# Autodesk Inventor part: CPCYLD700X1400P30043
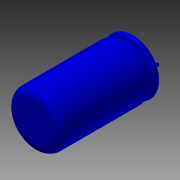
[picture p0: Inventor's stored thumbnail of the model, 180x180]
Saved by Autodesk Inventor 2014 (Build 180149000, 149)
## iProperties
Shininess: 64.0
Length Units: 11272
Angle Units: 11279
Time Units: 11290
Mass Units: 11286
Length Display Precision: 3
Angle Display Precision: 2
Compacted: True
Part Number: CPCYLD700X1400P30043
Document SubType Name: Modeling
Created: 2003-04
Designer: t_enrig
Manufacturer: Standard
Standards Organization: Custom
Density: 1 g/cm^3
Mass: 7.97163 g
Surface Area: 23.6175 cm^2
Volume: 7.97163 cm^3
Material: Generic
Appearance: TranslatedColorStyle
Density: 0.0
Volumn: 0.0
Area: 0.0
PropertySet Name: Model Information
Control State: 0
Master: False
Checked Out: False
Author: t_enrig
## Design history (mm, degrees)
feature "Base1"
body "Solid1"
